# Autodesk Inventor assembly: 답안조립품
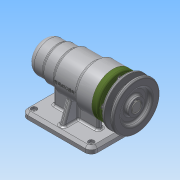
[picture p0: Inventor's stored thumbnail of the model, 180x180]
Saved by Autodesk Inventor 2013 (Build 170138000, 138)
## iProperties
Created: 2016-06
Part Number: 답안조립품
Document SubType Name: Assembly
Designer: Administrator
Author: Administrator
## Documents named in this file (12)
- C:\Users\Administrator\Desktop\460608V1007\답안조립품.iam
- C:\Users\Administrator\Desktop\460608V1007\본체.ipt
- C:\Users\Administrator\Desktop\460608V1007\베어링 6004.ipt
- C:\Users\Administrator\Desktop\460608V1007\커버.ipt
- C:\Users\Administrator\Desktop\460608V1007\볼트 M4 x 12.ipt
- C:\Users\Administrator\Desktop\460608V1007\오일 실.ipt
- C:\Users\Administrator\Desktop\460608V1007\축.ipt
- C:\Users\Administrator\Desktop\460608V1007\어댑터슬리브.ipt
- C:\Users\Administrator\Desktop\460608V1007\베어링 51202.ipt
- C:\Users\Administrator\Desktop\460608V1007\키 5 x 5 x 16.ipt
- C:\Users\Administrator\Desktop\460608V1007\V벨트풀리.ipt
- C:\Users\Administrator\Desktop\460608V1007\멈춤나사 M3x8.ipt
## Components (6 placed, 2 different names)
1. ISO 4762 M4 x 12:5
2. V벨트풀리:1 — 각도:2
3. ISO 4762 M4 x 12:1
4. ISO 4762 M4 x 12:2
5. ISO 4762 M4 x 12:3
6. ISO 4762 M4 x 12:4
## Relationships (1: Angle 1)
- 각도:2 [Angle]: V벨트풀리:1
